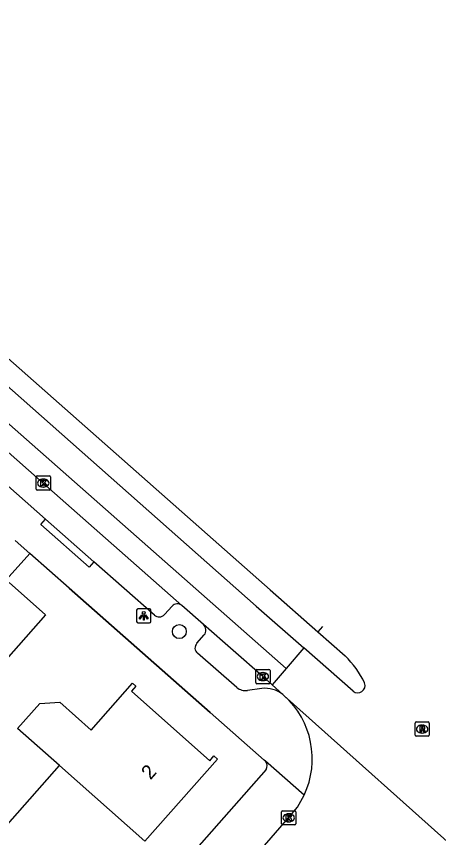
# Model space of a CAD drawing. Extents: x 162532 to 163264, y 381233 to 382042.
# Drawn here: x 162925 to 162954.6, y 381903 to 381960.6 of the extents above; entities that cross this region are included whole.
import ezdxf

# ---------------------------------------------------------------- set-up
doc = ezdxf.new("R2010")
doc.units = 0
for name, color, linetype in [('IMGEO_Boom', 7, 'Continuous'), ('IMGEO_Kolk', 7, 'Continuous'), ('IMGEO_Lichtpunt', 7, 'Continuous'), ('IMGEO_Muur', 7, 'Continuous'), ('IMGEO_Pand', 7, 'Continuous'), ('IMGEO_Pand_nummerreeks', 7, 'Continuous'), ('IMGEO_Rijbaan_lokaal_gesloten', 7, 'Continuous'), ('IMGEO_Rijbaan_lokaal_open', 7, 'Continuous'), ('IMGEO_Rioolput', 7, 'Continuous'), ('IMGEO_Voetpad_open', 7, 'Continuous')]:
    doc.layers.add(name, color=color, linetype=linetype)

msp = doc.modelspace()

# ---------------------------------------------------------------- linework, layer by layer
at = {"layer": 'IMGEO_Boom'}
msp.add_circle((162936.465, 381917.457), 0.489, dxfattribs=at)
at = {"layer": 'IMGEO_Kolk'}
for p, q in [((162926.421, 381927.439), (162926.421, 381928.291)), ((162926.496, 381928.365), (162927.348, 381928.365)), ((162926.909, 381928.145), (162926.934, 381928.145)), ((162927.422, 381928.291), (162927.422, 381927.439)), ((162927.348, 381927.365), (162926.496, 381927.365)), ((162926.932, 381927.585), (162926.907, 381927.585)), ((162941.824, 381913.878), (162941.824, 381914.73)), ((162941.899, 381914.804), (162942.751, 381914.804)), ((162942.825, 381914.73), (162942.825, 381913.878)), ((162942.312, 381914.584), (162942.337, 381914.584)), ((162942.751, 381913.804), (162941.899, 381913.804)), ((162942.335, 381914.024), (162942.31, 381914.024)), ((162943.71, 381904.905), (162944.562, 381904.905)), ((162943.635, 381903.979), (162943.635, 381904.831)), ((162944.123, 381904.685), (162944.148, 381904.685)), ((162944.636, 381904.831), (162944.636, 381903.979)), ((162944.562, 381903.905), (162943.71, 381903.905)), ((162944.146, 381904.125), (162944.121, 381904.125))]:
    msp.add_line(p, q, dxfattribs=at)
for points in [[(162926.421, 381927.439), (162926.421, 381928.291)], [(162926.496, 381928.365), (162927.348, 381928.365)], [(162926.742, 381928.065), (162926.865, 381928.065), (162926.865, 381927.914), (162926.995, 381928.065), (162927.159, 381928.065), (162927.013, 381927.914), (162927.166, 381927.665), (162927.014, 381927.665), (162926.929, 381927.829), (162926.865, 381927.762), (162926.865, 381927.665), (162926.742, 381927.665), (162926.742, 381928.065)], [(162927.422, 381928.291), (162927.422, 381927.439)], [(162927.348, 381927.365), (162926.496, 381927.365)], [(162941.824, 381913.878), (162941.824, 381914.73)], [(162941.899, 381914.804), (162942.751, 381914.804)], [(162942.825, 381914.73), (162942.825, 381913.878)], [(162942.145, 381914.504), (162942.268, 381914.504), (162942.268, 381914.353), (162942.398, 381914.504), (162942.562, 381914.504), (162942.416, 381914.353), (162942.569, 381914.104), (162942.417, 381914.104), (162942.332, 381914.268), (162942.268, 381914.201), (162942.268, 381914.104), (162942.145, 381914.104), (162942.145, 381914.504)], [(162942.751, 381913.804), (162941.899, 381913.804)], [(162943.71, 381904.905), (162944.562, 381904.905)], [(162943.635, 381903.979), (162943.635, 381904.831)], [(162943.956, 381904.605), (162944.079, 381904.605), (162944.079, 381904.454), (162944.209, 381904.605), (162944.373, 381904.605), (162944.227, 381904.454), (162944.38, 381904.205), (162944.228, 381904.205), (162944.143, 381904.369), (162944.079, 381904.302), (162944.079, 381904.205), (162943.956, 381904.205), (162943.956, 381904.605)], [(162944.636, 381904.831), (162944.636, 381903.979)], [(162944.562, 381903.905), (162943.71, 381903.905)]]:
    msp.add_lwpolyline(points, dxfattribs=at)
for centre, start, end in [((162926.498, 381928.289), 91.55205, 178.44795), ((162926.498, 381928.289), 91.55205, 178.44795), ((162927.346, 381928.289), 1.55205, 88.44795), ((162927.346, 381928.289), 1.55205, 88.44795), ((162926.498, 381927.441), 181.55205, 268.44795), ((162926.498, 381927.441), 181.55205, 268.44795), ((162927.346, 381927.441), 271.55205, 358.44795), ((162927.346, 381927.441), 271.55205, 358.44795), ((162941.901, 381914.728), 91.55205, 178.44795), ((162941.901, 381914.728), 91.55205, 178.44795), ((162942.749, 381914.728), 1.55205, 88.44795), ((162942.749, 381914.728), 1.55205, 88.44795), ((162941.901, 381913.88), 181.55205, 268.44795), ((162941.901, 381913.88), 181.55205, 268.44795), ((162942.749, 381913.88), 271.55205, 358.44795), ((162942.749, 381913.88), 271.55205, 358.44795), ((162943.712, 381904.829), 91.55205, 178.44795), ((162943.712, 381904.829), 91.55205, 178.44795), ((162944.56, 381904.829), 1.55205, 88.44795), ((162944.56, 381904.829), 1.55205, 88.44795), ((162943.712, 381903.981), 181.55205, 268.44795), ((162943.712, 381903.981), 181.55205, 268.44795), ((162944.56, 381903.981), 271.55205, 358.44795), ((162944.56, 381903.981), 271.55205, 358.44795)]:
    msp.add_arc(centre, 0.0765, start, end, dxfattribs=at)
for centre, major_axis, ratio, start_param, end_param in [((162926.908, 381927.865), (-0.387, 0.002), 0.722429, 4.712389, 7.853982), ((162926.933, 381927.865), (-0.39, 0.002), 0.717154, 1.570796, 4.712389), ((162942.311, 381914.304), (-0.387, 0.002), 0.722429, 4.712389, 7.853982), ((162942.336, 381914.304), (-0.39, 0.002), 0.717154, 1.570796, 4.712389), ((162944.122, 381904.405), (-0.387, 0.002), 0.722429, 4.712389, 7.853982), ((162944.147, 381904.405), (-0.39, 0.002), 0.717154, 1.570796, 4.712389)]:
    msp.add_ellipse(centre, major_axis=major_axis, ratio=ratio, start_param=start_param, end_param=end_param, dxfattribs=at)
at = {"layer": 'IMGEO_Lichtpunt'}
for p, q in [((162933.469, 381918.965), (162933.469, 381918.158)), ((162933.469, 381918.965), (162933.469, 381918.158)), ((162934.371, 381919.06), (162933.563, 381919.06)), ((162934.371, 381919.06), (162933.563, 381919.06)), ((162934.465, 381918.158), (162934.465, 381918.965)), ((162934.465, 381918.158), (162934.465, 381918.965)), ((162933.563, 381918.064), (162934.371, 381918.064)), ((162933.563, 381918.064), (162934.371, 381918.064))]:
    msp.add_line(p, q, dxfattribs=at)
for points in [[(162933.843, 381918.629), (162933.882, 381918.601), (162933.694, 381918.339), (162933.656, 381918.366), (162933.843, 381918.629)], [(162933.945, 381918.581), (162933.992, 381918.581), (162933.992, 381918.259), (162933.945, 381918.259), (162933.945, 381918.581)], [(162934.055, 381918.601), (162934.093, 381918.628), (162934.28, 381918.366), (162934.241, 381918.338), (162934.055, 381918.601)]]:
    msp.add_lwpolyline(points, dxfattribs=at)
msp.add_circle((162933.968, 381918.763), 0.0994, dxfattribs=at)
for centre, start, end in [((162933.563, 381918.965), 90, 180), ((162933.563, 381918.965), 90, 180), ((162934.371, 381918.965), 0, 90), ((162934.371, 381918.965), 0, 90), ((162933.563, 381918.158), 180, 270), ((162933.563, 381918.158), 180, 270), ((162934.371, 381918.158), 270, 0), ((162934.371, 381918.158), 270, 360)]:
    msp.add_arc(centre, 0.0946, start, end, dxfattribs=at)
at = {"layer": 'IMGEO_Muur'}
msp.add_lwpolyline([(162928.735, 381920.502), (162938.619, 381911.798)], dxfattribs=at)
at = {"layer": 'IMGEO_Pand'}
for points in [[(162920.356, 381916.189), (162924.525, 381920.895), (162927.079, 381918.633), (162922.91, 381913.927), (162922.346, 381914.427)], [(162928.053, 381908.062), (162925.122, 381910.665), (162926.683, 381912.422), (162928.073, 381912.512), (162930.271, 381910.559), (162933.186, 381913.84), (162933.424, 381913.628), (162933.113, 381913.278), (162938.593, 381908.409), (162938.889, 381908.742), (162939.14, 381908.519), (162934.034, 381902.771)], [(162923.528, 381902.968), (162928.053, 381908.062)], [(162934.034, 381902.771), (162928.053, 381908.062)]]:
    msp.add_lwpolyline(points, dxfattribs=at)
at = {"layer": 'IMGEO_Rijbaan_lokaal_gesloten'}
for points in [[(162897.288, 381960.567), (162901.017, 381957.279), (162942.827, 381920.385), (162946.168, 381917.444)], [(162896.307, 381959.47), (162900.119, 381956.128), (162941.853, 381919.239), (162945.194, 381916.309)], [(162943.951, 381914.87), (162918.586, 381937.208), (162895.023, 381958.025)], [(162936.646, 381919.286), (162926.918, 381927.866), (162924.026, 381930.413)], [(162938.158, 381917.949), (162936.646, 381919.286)], [(162942.966, 381913.731), (162942.321, 381914.305), (162938.158, 381917.949)], [(162946.513, 381917.818), (162946.168, 381917.444)], [(162945.194, 381916.309), (162943.951, 381914.87)], [(162943.951, 381914.87), (162942.966, 381913.731)]]:
    msp.add_lwpolyline(points, dxfattribs=at)
at = {"layer": 'IMGEO_Rijbaan_lokaal_open'}
for points in [[(162946.168, 381917.444), (162948.095, 381915.748)], [(162948.646, 381913.28), (162945.194, 381916.309)], [(162942.966, 381913.731), (162943.728, 381913.052)], [(162943.728, 381913.052), (162943.829, 381912.962)], [(162943.829, 381912.962), (162957.204, 381901.001), (162957.238, 381900.957)], [(162941.214, 381901.059), (162944.133, 381904.404), (162944.745, 381905.159), (162945.226, 381906.002)]]:
    msp.add_lwpolyline(points, dxfattribs=at)
for centre, radius, start, end in [((162943.696, 381911.142), 6.369, 25.24041, 46.31526), ((162948.974, 381913.677), 0.515, 230.43284, 20.52214), ((162939.808, 381908.535), 5.981, 334.94503, 47.75398)]:
    msp.add_arc(centre, radius, start, end, dxfattribs=at)
at = {"layer": 'IMGEO_Rioolput'}
for p, q in [((162952.996, 381910.197), (162952.996, 381911.049)), ((162953.071, 381911.123), (162953.923, 381911.123)), ((162953.484, 381910.903), (162953.509, 381910.903)), ((162953.997, 381911.049), (162953.997, 381910.197)), ((162953.923, 381910.123), (162953.071, 381910.123)), ((162953.507, 381910.343), (162953.482, 381910.343))]:
    msp.add_line(p, q, dxfattribs=at)
for points in [[(162952.996, 381910.197), (162952.996, 381911.049)], [(162953.071, 381911.123), (162953.923, 381911.123)], [(162953.585, 381910.821), (162953.333, 381910.823), (162953.333, 381910.423)], [(162953.511, 381910.742), (162953.457, 381910.742), (162953.457, 381910.661)], [(162953.457, 381910.661), (162953.509, 381910.661)], [(162953.997, 381911.049), (162953.997, 381910.197)], [(162953.923, 381910.123), (162953.071, 381910.123)], [(162953.333, 381910.423), (162953.457, 381910.423), (162953.457, 381910.585), (162953.468, 381910.585)], [(162953.515, 381910.556), (162953.586, 381910.423), (162953.726, 381910.423), (162953.661, 381910.549)]]:
    msp.add_lwpolyline(points, dxfattribs=at)
for centre, radius, start, end in [((162953.073, 381911.047), 0.0765, 91.55205, 178.44795), ((162953.073, 381911.047), 0.0765, 91.55205, 178.44795), ((162953.493, 381910.85), 0.19, 274.7715, 282.96867), ((162953.517, 381910.646), 0.0964, 77.00612, 93.18647), ((162953.531, 381910.703), 0.0378, 276.66336, 79.67722), ((162953.584, 381910.711), 0.109, 350.36119, 89.41601), ((162953.582, 381910.711), 0.112, 277.58423, 350.98172), ((162953.921, 381911.047), 0.0765, 1.55205, 88.44795), ((162953.921, 381911.047), 0.0765, 1.55205, 88.44795), ((162953.073, 381910.199), 0.0765, 181.55205, 268.44795), ((162953.073, 381910.199), 0.0765, 181.55205, 268.44795), ((162953.467, 381910.532), 0.0533, 26.02933, 88.69889), ((162953.566, 381910.496), 0.108, 29.51342, 73.79051), ((162953.921, 381910.199), 0.0765, 271.55205, 358.44795), ((162953.921, 381910.199), 0.0765, 271.55205, 358.44795)]:
    msp.add_arc(centre, radius, start, end, dxfattribs=at)
for centre, major_axis, ratio, start_param, end_param in [((162953.483, 381910.623), (-0.387, 0.002), 0.722429, 4.712389, 7.853982), ((162953.508, 381910.623), (-0.39, 0.002), 0.717154, 1.570796, 4.712389)]:
    msp.add_ellipse(centre, major_axis=major_axis, ratio=ratio, start_param=start_param, end_param=end_param, dxfattribs=at)
at = {"layer": 'IMGEO_Voetpad_open'}
for points in [[(162927.073, 381925.34), (162923.598, 381928.394)], [(162930.46, 381922.342), (162930.129, 381921.968), (162926.742, 381924.966), (162927.073, 381925.34)], [(162927.073, 381925.34), (162930.46, 381922.342)], [(162925.969, 381922.938), (162924.95, 381923.835)], [(162925.969, 381922.938), (162906.839, 381901.692), (162905.317, 381903.044)], [(162942.509, 381908.372), (162942.415, 381908.454), (162938.619, 381911.798), (162928.735, 381920.502), (162925.969, 381922.938)], [(162934.713, 381918.608), (162930.46, 381922.342)], [(162935.952, 381919.242), (162935.43, 381918.644)], [(162937.699, 381916.637), (162938.213, 381917.22)], [(162940.499, 381913.544), (162937.74, 381915.935)], [(162942.24, 381913.473), (162941.247, 381913.336)], [(162945.226, 381906.002), (162942.509, 381908.372)], [(162942.548, 381907.783), (162932.776, 381896.712), (162917.749, 381879.811)]]:
    msp.add_lwpolyline(points, dxfattribs=at)
for centre, radius, start, end in [((162936.323, 381918.893), 0.509, 50.53256, 136.72289), ((162935.053, 381919.004), 0.521, 229.37736, 316.37136), ((162937.763, 381917.553), 0.56, 323.52435, 45.10475), ((162938.035, 381916.304), 0.473, 135.28354, 231.40154), ((162941.101, 381914.262), 0.937, 229.98362, 278.93656), ((162942.47, 381911.445), 2.041, 51.9406, 96.46379), ((162942.143, 381908.052), 0.486, 326.41142, 41.16507)]:
    msp.add_arc(centre, radius, start, end, dxfattribs=at)

# ---------------------------------------------------------------- texts
at = {"layer": 'IMGEO_Pand_nummerreeks'}
msp.add_text('2', height=1, rotation=48.38122, dxfattribs=at).set_placement((162934.442, 381907.025))

doc.saveas('drawing.dxf')
